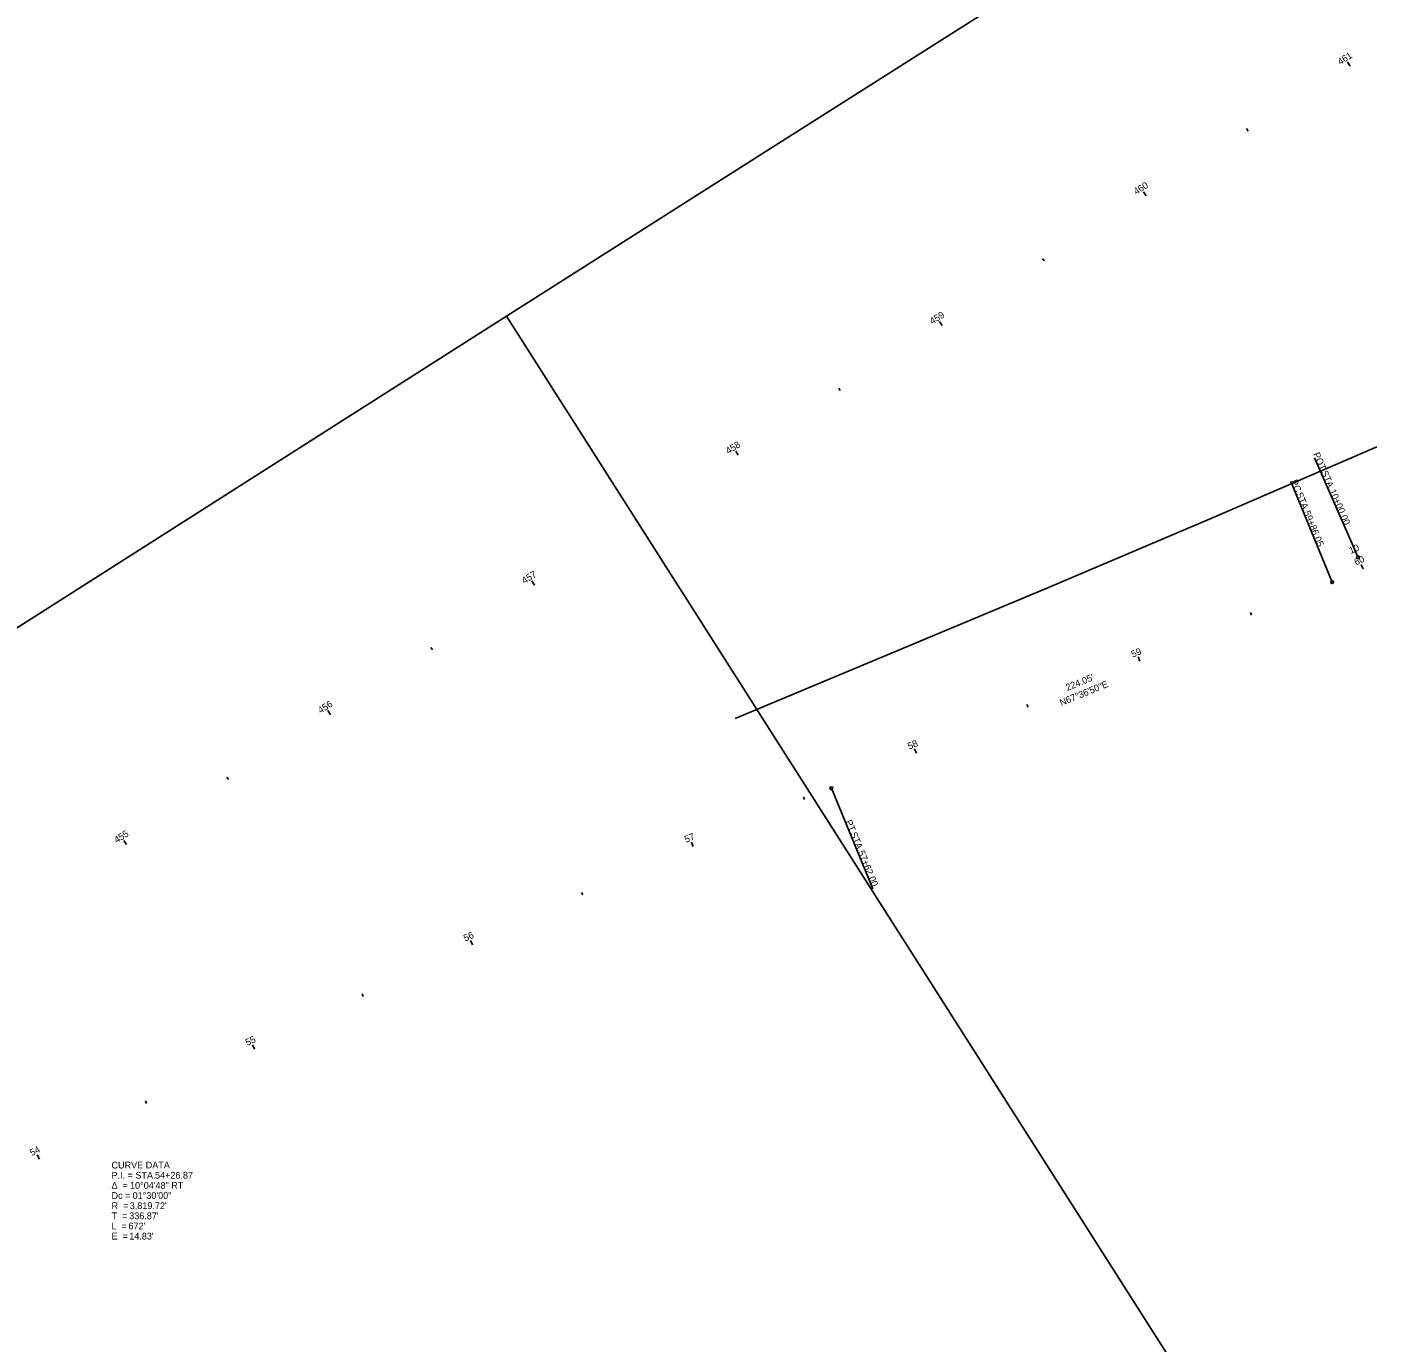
# Model space of a CAD drawing. Extents: x 143421 to 147121, y 511505 to 514560.
# Drawn here: x 144277 to 144835, y 512595 to 513139 of the extents above; entities that cross this region are included whole.
import ezdxf

# ---------------------------------------------------------------- set-up
doc = ezdxf.new("R2010")
doc.units = 0
for name, color, linetype in [('CM_Corridor_Conceptual', 7, 'Continuous'), ('CM_Corridor_Range_Conceptual', 7, 'Continuous'), ('DR_P_Sediment_Basin', 7, 'Continuous'), ('DR_Pond', 7, 'Continuous'), ('DT_P_Tie', 7, 'Continuous'), ('DT_X_Contour_Major', 7, 'Continuous'), ('DT_X_Triangles', 7, 'Continuous'), ('DT_X_Void', 7, 'Continuous'), ('SC_Scratch1', 7, 'Continuous'), ('SC_Scratch2', 7, 'Continuous')]:
    doc.layers.add(name, color=color, linetype=linetype)

msp = doc.modelspace()

# ---------------------------------------------------------------- linework, layer by layer
at = {"layer": 'CM_Corridor_Conceptual'}
for p, q in [((144829.55, 512915.02), (144828.75, 512916.85)), ((144783.38, 512895.83), (144782.92, 512896.94)), ((144737.15, 512876.79), (144736.39, 512878.64)), ((144690.92, 512857.75), (144690.46, 512858.86)), ((144644.68, 512838.71), (144643.92, 512840.56)), ((144598.46, 512819.65), (144598, 512820.76)), ((144552.41, 512800.16), (144551.62, 512801.99)), ((144506.63, 512780.07), (144506.14, 512781.16)), ((144461.11, 512759.38), (144460.27, 512761.2)), ((144415.87, 512738.1), (144415.35, 512739.18)), ((144370.9, 512716.23), (144370.02, 512718.02)), ((144326.23, 512693.77), (144325.69, 512694.84)), ((144281.86, 512670.73), (144280.93, 512672.49))]:
    msp.add_line(p, q, dxfattribs=at)
at = {"layer": 'DR_Pond'}
for points in [[(144475.14, 513019.58), (145011.95, 512175.87), (145117.41, 512242.97), (145222.87, 512310.07), (145328.34, 512377.17), (145433.8, 512444.27), (145539.26, 512511.37), (145644.73, 512578.47), (145750.19, 512645.57), (145855.65, 512712.67), (145961.12, 512779.77), (146066.58, 512846.87), (145529.78, 513690.58), (145424.32, 513623.48), (145318.85, 513556.38), (145213.39, 513489.28), (145107.93, 513422.18), (145002.46, 513355.08), (144897, 513287.98), (144791.53, 513220.88), (144686.07, 513153.78), (144580.61, 513086.68)], [(143420.51, 512348.57), (143957.31, 511504.87), (144062.77, 511571.97), (144168.24, 511639.07), (144273.7, 511706.17), (144379.16, 511773.27), (144484.63, 511840.37), (144590.09, 511907.47), (144695.55, 511974.57), (144801.02, 512041.67), (144906.48, 512108.77), (145011.95, 512175.87), (144475.14, 513019.58), (144369.68, 512952.48), (144264.22, 512885.38), (144158.75, 512818.28), (144053.29, 512751.18), (143947.83, 512684.08), (143842.36, 512616.98), (143736.9, 512549.88), (143631.44, 512482.77), (143525.97, 512415.67)]]:
    msp.add_lwpolyline(points, close=True, dxfattribs=at)
at = {"layer": 'DT_P_Tie'}
msp.add_line((144827.47, 512919.78), (144809.42, 512961), dxfattribs=at)
msp.add_circle((144827.47, 512919.78), 0.6, dxfattribs=at)
at = {"layer": 'DT_X_Contour_Major'}
for p, q in [((144824.12, 513123.09), (144823.05, 513124.77)), ((144781.94, 513096.25), (144781.29, 513097.26)), ((144739.75, 513069.41), (144738.68, 513071.09)), ((144697.57, 513042.57), (144696.92, 513043.58)), ((144655.38, 513015.73), (144654.31, 513017.41)), ((144613.19, 512988.89), (144612.55, 512989.9)), ((144571.01, 512962.05), (144569.94, 512963.73)), ((144528.82, 512935.21), (144528.18, 512936.22)), ((144486.64, 512908.37), (144485.56, 512910.05)), ((144444.45, 512881.53), (144443.81, 512882.54)), ((144402.27, 512854.69), (144401.19, 512856.37)), ((144360.08, 512827.85), (144359.44, 512828.86)), ((144317.9, 512801.01), (144316.82, 512802.69))]:
    msp.add_line(p, q, dxfattribs=at)
at = {"layer": 'DT_X_Triangles'}
msp.add_line((144827.47, 512919.78), (144826.67, 512921.61), dxfattribs=at)
at = {"layer": 'DT_X_Void'}
msp.add_lwpolyline([(144835.2, 512965.61), (144767.24, 512936.14), (144699.36, 512907.28), (144569.68, 512853.15)], dxfattribs=at)
at = {"layer": 'SC_Scratch2'}
for p, q in [((144816.71, 512909.56), (144799.57, 512951.17)), ((144609.55, 512824.24), (144626.69, 512782.63))]:
    msp.add_line(p, q, dxfattribs=at)
for centre in [(144816.71, 512909.56), (144609.55, 512824.24)]:
    msp.add_circle(centre, 0.6, dxfattribs=at)

# ---------------------------------------------------------------- texts
at = {"layer": 'CM_Corridor_Conceptual'}
for s, rotation, p in [('60', 23.642, (144826.58, 512916.45)), ('59', 22.3862, (144734.25, 512878.3)), ('58', 22.3862, (144641.76, 512840.21)), ('57', 23.3162, (144549.47, 512801.61)), ('56', 24.8162, (144458.12, 512760.75)), ('55', 26.3162, (144367.92, 512717.54)), ('54', 27.8162, (144278.78, 512671.93))]:
    msp.add_text(s, height=2.8, rotation=rotation, dxfattribs=at).set_placement(p)
at = {"layer": 'CM_Corridor_Range_Conceptual'}
msp.add_text("224.05'", height=2.8, rotation=22.3862, dxfattribs=at).set_placement((144707.16, 512864.48))
at = {"layer": 'DR_P_Sediment_Basin'}
for s, p in [('CURVE DATA', (144311.7, 512666.87)), ('P.I. = STA. ', (144311.7, 512662.67)), ('54+26.87', (144329.69, 512662.67)), ('Δ  = ', (144311.7, 512658.47)), ('10°04\'48" RT', (144319.34, 512658.47)), ('Dc = ', (144311.7, 512654.27)), ('R  = ', (144311.7, 512650.07)), ("3,819.72'", (144319.23, 512650.07)), ('01°30\'00"', (144320.44, 512654.27)), ('T  = ', (144311.7, 512645.87)), ("336.87'", (144319.02, 512645.87)), ('L  = ', (144311.7, 512641.67)), ("672'", (144318.73, 512641.67)), ('E  = ', (144311.7, 512637.47)), ("14.83'", (144319.04, 512637.47))]:
    msp.add_text(s, height=2.8, dxfattribs=at).set_placement(p)
at = {"layer": 'DT_P_Tie'}
for s, p in [('POT', (144808.79, 512962.56)), (' STA. ', (144811.68, 512955.96)), ('10+00.00', (144815.47, 512947.3))]:
    msp.add_text(s, height=2.8, rotation=293.642, dxfattribs=at).set_placement(p)
at = {"layer": 'DT_X_Contour_Major'}
for s, p in [('461', (144820.06, 513123.47)), ('460', (144735.65, 513069.76)), ('459', (144651.32, 513016.1)), ('458', (144566.93, 512962.41)), ('457', (144482.56, 512908.73)), ('456', (144398.18, 512855.05)), ('455', (144313.85, 512801.39))]:
    msp.add_text(s, height=2.8, rotation=32.4662, dxfattribs=at).set_placement(p)
at = {"layer": 'DT_X_Triangles'}
msp.add_text('10', height=2.8, rotation=23.642, dxfattribs=at).set_placement((144824.43, 512921.17))
at = {"layer": 'SC_Scratch1'}
msp.add_text('N67°36\'50"E', height=2.8, rotation=22.3862, dxfattribs=at).set_placement((144704.68, 512858.23))
at = {"layer": 'SC_Scratch2'}
for s, p in [('PC', (144799.54, 512951.33)), (' STA. ', (144801.3, 512947.08)), ('59+86.05', (144804.85, 512938.46)), ('PT', (144615.26, 512810.47)), (' STA. ', (144616.92, 512806.44)), ('57+62.00', (144620.47, 512797.82))]:
    msp.add_text(s, height=2.8, rotation=292.3862, dxfattribs=at).set_placement(p)

doc.saveas('drawing.dxf')
